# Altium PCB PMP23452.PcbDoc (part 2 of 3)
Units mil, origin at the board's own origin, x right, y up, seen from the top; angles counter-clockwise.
Board outline 4000 x 4000 mil, 6 copper layers (Top Layer, Layer 2, Layer 3, Layer 4, Layer 5, Bottom Layer), stack 40.224 mil thick; 235 components, 68 nets, 526 pads, 358 vias.
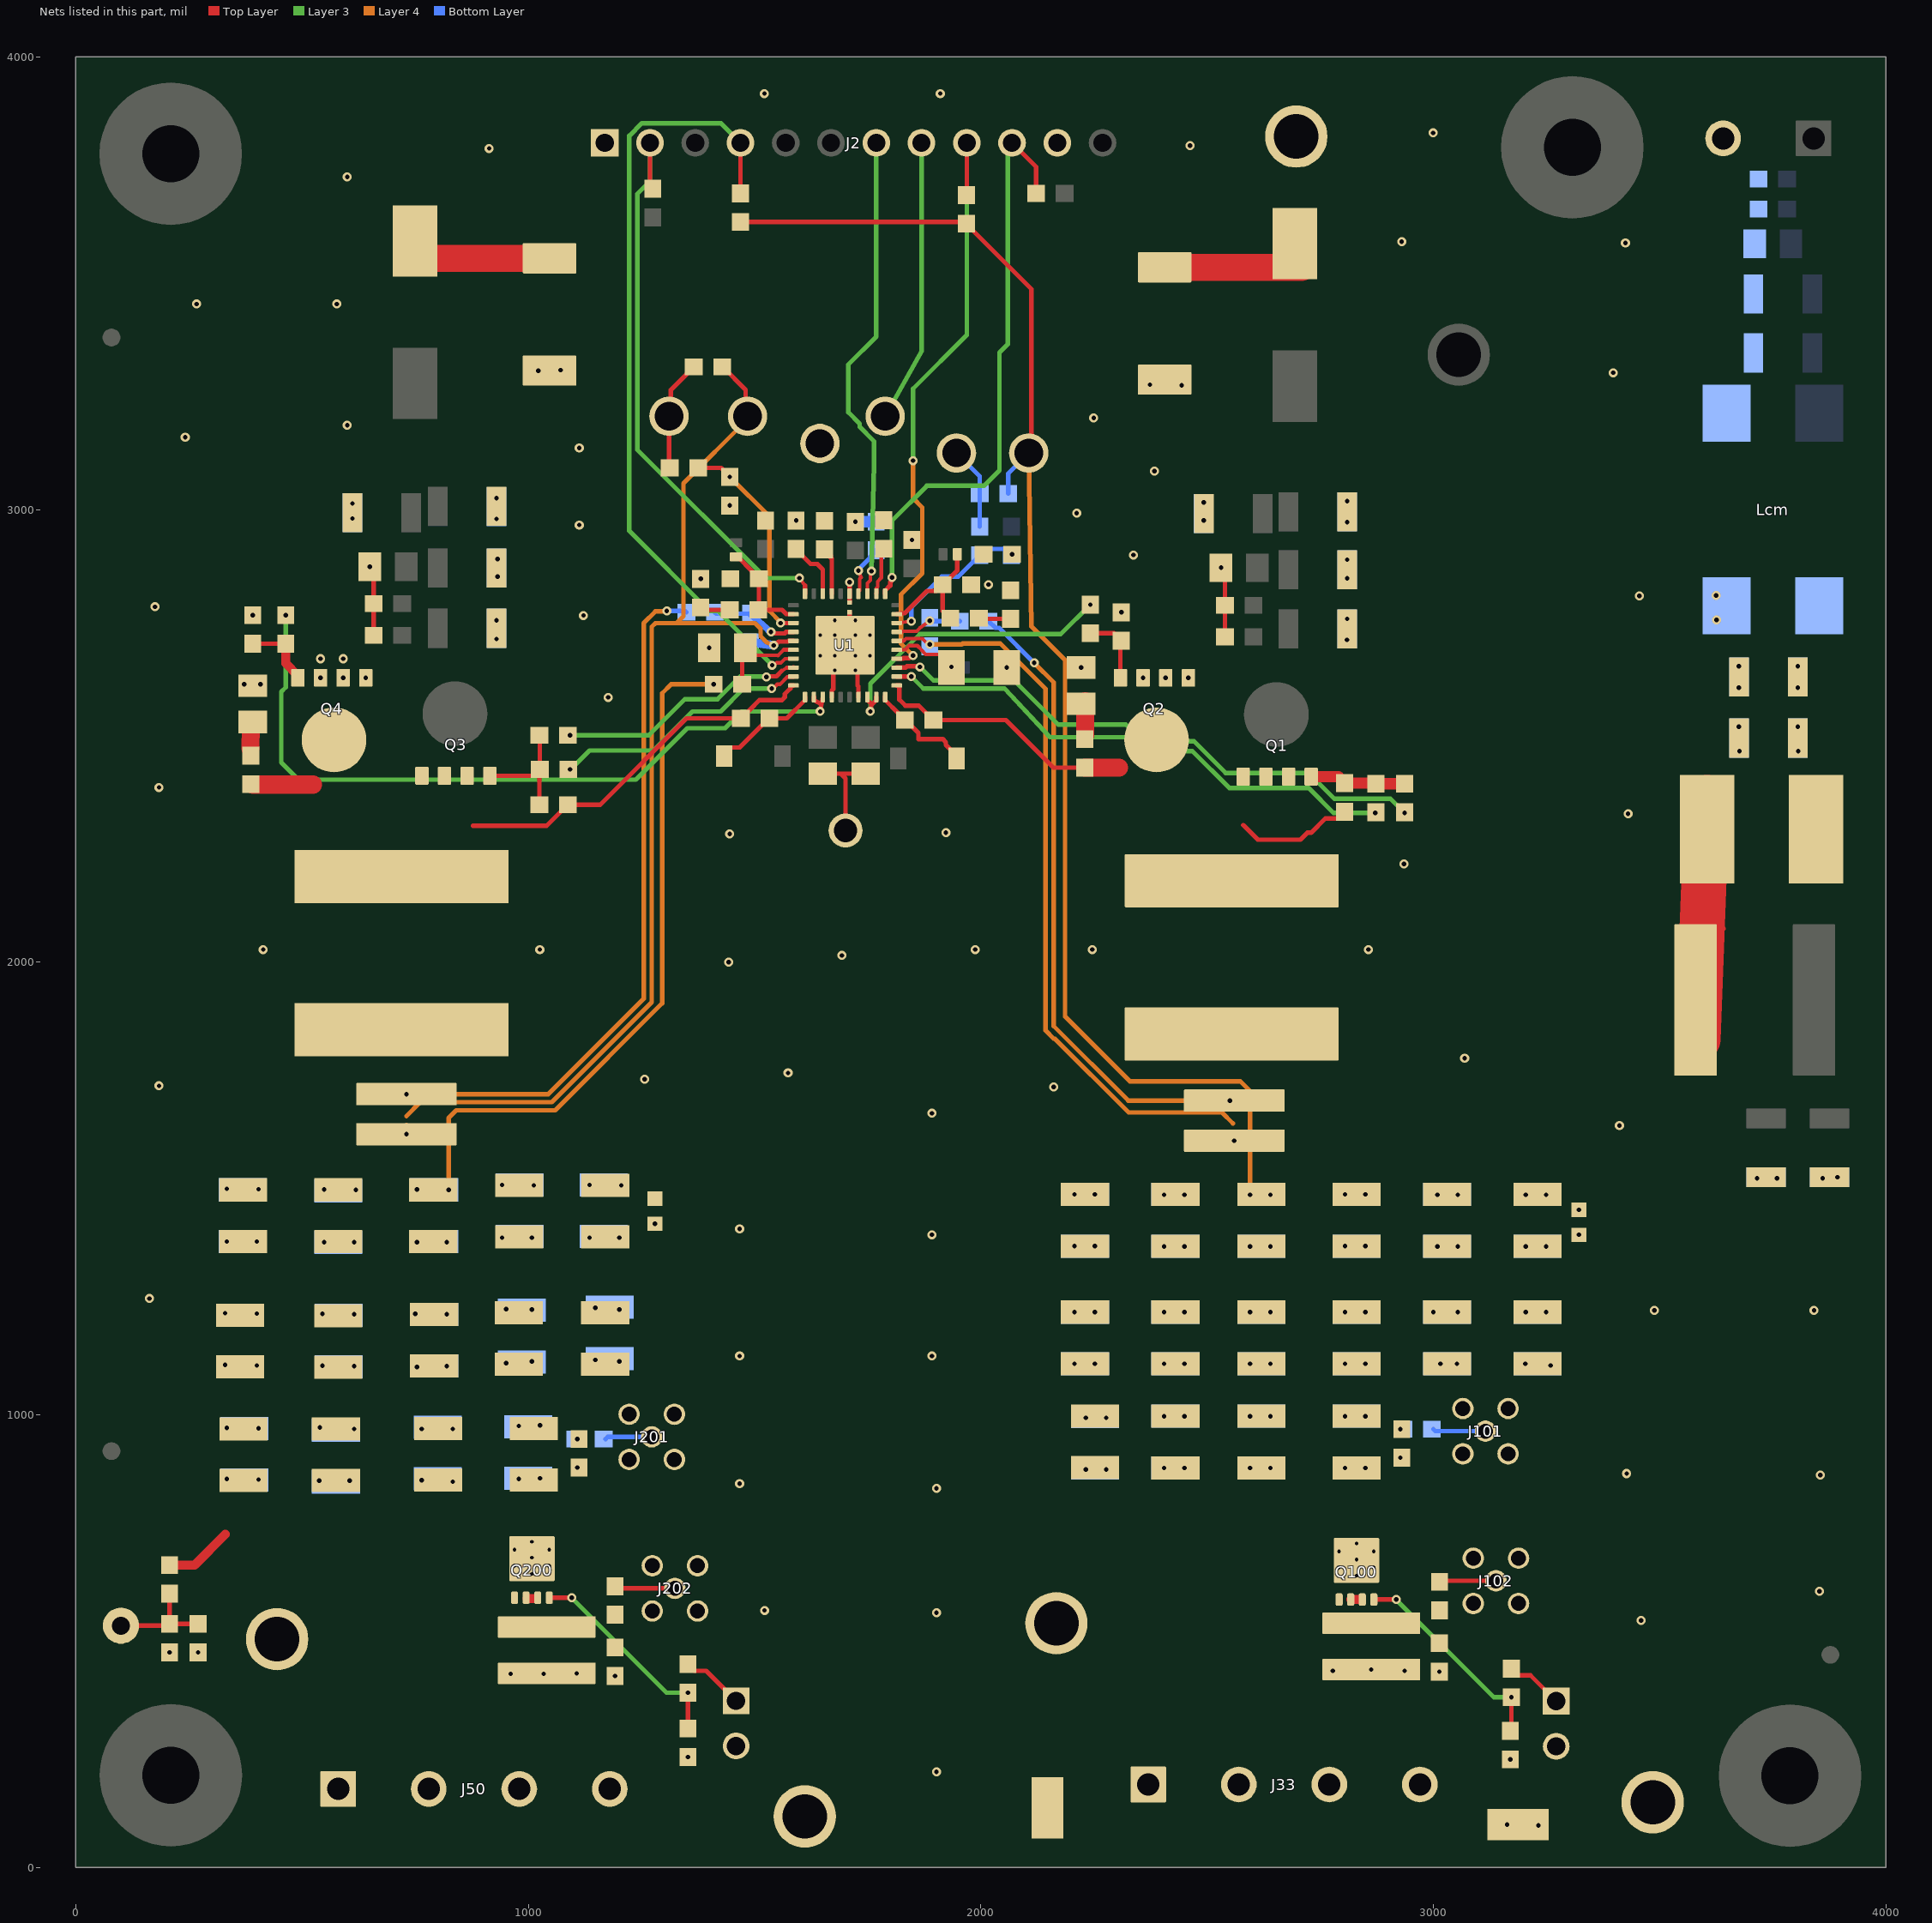
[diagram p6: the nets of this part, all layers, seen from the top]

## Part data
C1 C2 C5: library part CMP-0083622-1, "CAP, CERM, 2.2 µF, 25 V,+/- 10%, X7R, AEC-Q200 Grade 1, 0805", Cap_Case=0805, Manufacturer=MuRata, Supplier Part Number 1=490-4787-1-ND, TempCo=X7R, Tolerance_%=10%, Value2=25V, ValueDisplayed=2.2µF
C3: library part CMP-0008781-2, "CAP, CERM, 0.47 uF, 100 V, +/- 10%, X7R, AEC-Q200 Grade 1, 1206", Cap_Case=1206_180, Manufacturer=TDK, Supplier Part Number 1=445-5844-1-ND, TempCo=X7R, Tolerance_%=10%, Value1="0.007558 ohm", Value2=100V, ValueDisplayed=0.47uF
C4: library part CMP-0007138-4, "CAP, CERM, 0.47 uF, 16 V, +/- 10%, X7R, AEC-Q200 Grade 1, 0603", Cap_Case=0603, Manufacturer=MuRata, Supplier Part Number 1=490-4775-1-ND, TempCo=X7R, Tolerance_%=10%, Value1=Unknown, Value2=16V, ValueDisplayed=0.47uF
C6 C7 C30 C63 C101 C102 C201 C202 Csns5V Css1 Css2: library part CMP-0007077-5, "CAP, CERM, 0.1 uF, 25 V, +/- 10%, X7R, AEC-Q200 Grade 1, 0603", Cap_Case=0603, Manufacturer=TDK, Supplier Part Number 1=445-5667-1-ND, TempCo=X7R, Tolerance_%=10%, Value1=Unknown, Value2=25V, ValueDisplayed=0.1uF
C8 C9 C11 C12 C13 C14 C15 C19 C21 C22 C23 C24 C25 C29 C92 C93 C94 C95 C96 C97 Cpi1 Cpi2 Cpi3 Cpi4 Cpi5 Cpi6: library part CMP-0085951-1, "CAP, CERM, 10 µF, 75 V,+/- 20%, X7R, AEC-Q200 Grade 1, 1210", Cap_Case=1210, Manufacturer=TDK, TempCo=X7R, Tolerance_%=20%, Value2=75V, ValueDisplayed=10µF
C10 C20: library part CMP-0012603-3, "CAP, Polymer Hybrid, 47 uF, 80 V, +/- 20%, 36 mohm, 10x10 SMD", Manufacturer=Panasonic, Supplier Part Number 1=P15469CT-ND, Tolerance_%=20%, Value1="0.036 ohm", Value2=63V, ValueDisplayed=47uF
C16 C26 Cpi7: library part CMP-0007969-2, "CAP, CERM, 0.1 uF, 100 V, +/- 10%, X7R, AEC-Q200 Grade 1, 0805", Cap_Case=0805, Manufacturer=TDK, Supplier Part Number 1=445-5827-1-ND, TempCo=X7R, Tolerance_%=10%, Value1="0.020726 ohm", Value2=100V, ValueDisplayed=0.1uF
C17 C27 Cpi8: library part CMP-0007082-4, "CAP, CERM, 0.01 uF, 100 V, +/- 10%, X7R, AEC-Q200 Grade 1, 0603", Cap_Case=0603, Manufacturer=TDK, Supplier Part Number 1=445-5812-1-ND, TempCo=X7R, Tolerance_%=10%, Value1="0.235428 ohm", Value2=100V, ValueDisplayed=0.01uF
C18 C28 Cpi9: library part CMP-0007081-4, "CAP, CERM, 1000 pF, 100 V, +/- 10%, X7R, AEC-Q200 Grade 1, 0603", Cap_Case=0603, Manufacturer=TDK, Supplier Part Number 1=445-5806-1-ND, TempCo=X7R, Tolerance_%=10%, Value1="1.97137 ohm", Value2=100V, ValueDisplayed=1000pF
C31 C32 C33 C34 C35 C36 C37 C38 C39 C40 C41 C42 C43 C44 C45 C46 C47 C48 C49 C50 C51 C52 C53 C54 C55 C56 C57 C58 C59 C60 C61 C62 C64 C65 C66 C67 C68 C69 C70 C71 C72 C73 C74 C75 C76 C77 C78 C79 C80 C81 C82 C83 C84 C85 C86 C87 C88 C89 C90 C91: library part CMP-0009221-2, "CAP, CERM, 47 uF, 10 V, +/- 20%, X7R, 1210", Cap_Case=1210, Manufacturer=MuRata, Supplier Part Number 1=490-6543-1-ND, TempCo=X7R, Tolerance_%=20%, Value1=Unknown, Value2=10V, ValueDisplayed=47uF
Ccomp1 Ccomp2: library part CMP-0007089-5, "CAP, CERM, 6800 pF, 100 V, +/- 10%, X7R, AEC-Q200 Grade 1, 0603", Cap_Case=0603, Manufacturer=TDK, Supplier Part Number 1=445-5811-1-ND, TempCo=X7R, Tolerance_%=10%, Value1="0.35202 ohm", Value2=100V, ValueDisplayed=6800pF
Ccs1 Ccs2: library part CMP-0006897-4, "CAP, CERM, 2200 pF, 50 V, +/- 10%, X7R, 0603", Cap_Case=0603, Manufacturer=Kemet, Supplier Part Number 1=1362428, TempCo=X7R, Tolerance_%=10%, Value1=Unknown, Value2=50V, ValueDisplayed=2200pF
Cdith: library part CMP-0007468-5, "CAP, CERM, 0.01 uF, 100 V, +/- 10%, X7R, 0603", Cap_Case=0603, Manufacturer=MuRata, Supplier Part Number 1=GRM188R72A103KA01D-ND, TempCo=X7R, Tolerance_%=10%, Value1=Unknown, Value2=100V, ValueDisplayed=0.01uF
Chf1 Chf2: library part CMP-0080062-1, "CAP, CERM, 47 pF, 50 V,+/- 5%, C0G/NP0, AEC-Q200 Grade 0, 0603", Cap_Case=0603, Manufacturer=TDK, PartNumber=CGA3E2NP01H470J080AA, Supplier Part Number 1=445-12417-1-ND, TempCo=C0G/NP0, Tolerance_%=5%, Value2=50V, ValueDisplayed=47pF
Cres: library part CMP-0080102-1, "CAP, CERM, 0.22 µF, 16 V,+/- 10%, X7R, AEC-Q200 Grade 1, 0603", Cap_Case=0603, Manufacturer=Samsung, Supplier Part Number 1=1276-6868-1-ND, TempCo=X7R, Tolerance_%=10%, Value2=16V, ValueDisplayed=0.22µF
Csnu1 Csnu2: library part CMP-0007259-4, "CAP, CERM, 27 pF, 100 V, +/- 5%, C0G/NP0, 0603", Cap_Case=0603, Manufacturer=MuRata, Supplier Part Number 1=490-1337-1-ND, TempCo=C0G/NP0, Tolerance_%=5%, Value1=Unknown, Value2=100V, ValueDisplayed=27pF
D1 D3: library part CMP-0080760-2, "Diode, Schottky, 100 V, 0.15 A, AEC-Q101, SOD-123", Manufacturer=Vishay-Semiconductor, Value1=0.15A, Value2=1V
D2 D4 D5: library part CMP-0098370-1, "Diode Schottky 100V 250mA Surface Mount DFN1006BD-2", Digikey Part Number=1727-BAT46LS-QYLCT-ND, Forward Current=250mA, Manufacturer=Nexperia, Max Surge Forward Current=2.5A, Mouser Part Number=771-BAT46LS-QYL, Operating Temperature Range="to +150°C", Peak Reverse Current=9uA, ValueDisplayed=25pF
FID1 FID2 FID3: library part CMP-0077181-1, "Fiducial mark.  There is nothing to buy or mount.", Manufacturer=N/A
H3 H4 H5 H6: library part CMP-0003610-1, "Standoff, Hex, 0.5\"L #4-40 Nylon", Manufacturer=Keystone, Supplier Part Number 1=36-1902C-ND
H7 H8 H9 H10: library part CMP-0003617-1, "Machine Screw, Round, #4-40 x 1/4, Nylon, Philips panhead", Manufacturer="B&F Fastener Supply", Supplier Part Number 1=H542-ND
J1: library part CMP-0055161-1, "TEST POINT SLOTTED .118\", TH", Manufacturer=Keystone, Supplier Part Number 1=36-1040-ND
J2: library part CMP-0054586-1, "Header, 2.54 mm, 12x1, Gold, TH", Color=Black, Current_A=3A, Manufacturer="Sullins Connector Solutions", Supplier Part Number 1=S1021E-12-ND, Voltage_V=1.8kV
J11: library part CMP-0074910-1, "Terminal Block, 5.08 mm, 2x1, Brass, TH", Color=Blue, Current_A=15A, Manufacturer="On-Shore Technology", Supplier Part Number 1=ED1609-ND, Voltage_V=300V
J33 J50: library part CMP-0074939-1, "Terminal Block, 5.08 mm, 4x1, Brass, TH", Color=Blue, Current_A=15A, Manufacturer="On-Shore Technology", Supplier Part Number 1=ED2227-ND, Voltage_V=300V
J100 J200: library part CMP-0054947-1, "Header, 100mil, 2x1, Gold, TH", Manufacturer="TE Connectivity"
J101 J102 J201 J202: library part CMP-0075554-1, "Connector, MMCX 50 ohm, TH", Manufacturer=Samtec, Supplier Part Number 1=88K0549
L1: library part CMP-0090553-1, "XAL1350 Series Shielded Power Inductors 23A as RMS Current, 1 MHz Test Frequency, 30% Tolerance, 1.3uH and AEC Qualified Grade 1", Manufacturer=Coilcraft, Operating Temperature Range="to +165°C", Self Resonant Frequency=33MHz, Test Frequency=1MHz, Tolerance_%=20%
L2: library part CMP-0060967-1, "Inductor, Shielded, Composite, 2.2 uH, 24 A, 0.0042 ohm, SMD", Manufacturer=Coilcraft, Value1="0.0042 ohm", Value2=24A, ValueDisplayed=2.2uH
Lcm: library part CMP-0013118-2, "Coupled inductor, 8 A, 0.006 ohm, SMD", Manufacturer=TDK, Supplier Part Number 1=445-2212-1-ND
Logo1: library part CMP-0074844-1
LOGO2: library part CMP-0074837-2, "IEC 61010-1 Hot Surface Warning", Manufacturer="Texas Instruments"
Logo3: library part CMP-0074838-1, "Texas Instrument Corporate Signature"
Logo4: library part CMP-0074847-1, "FCC_disclaimer"
Logo5: library part CMP-0074769-3, Manufacturer="Texas Instruments"
Lpi: library part CMP-0120492-1, "10 µH Shielded Molded Inductor 12.1 A 18mOhm Max Nonstandard", Digikey Part Number=2457-XGL1060-103MEC-ND, Manufacturer=Coilcraft, Operating Temperature Range=to, Self Resonant Frequency=12MHz, Test Frequency=1MHz, Tolerance_%=20%
Lpi-hf: library part CMP-0003396-1, "Ferrite Bead, 800 ohm @ 100 MHz, 8 A, 2220", Manufacturer="Laird-Signal Integrity Products", Supplier Part Number 1=240-2433-1-ND, Value1="0.01 ohm", Value2=8A, ValueDisplayed="800 ohm"
NT1 NTv1 NTv2: library part CMP-0078142-6, "Single point connection between nets.", Manufacturer=N/A
Q1: library part CMP-0120369-1, "MOSFET N-Channel 80 V 13A (Ta), 59A (Tc) 3.7W (Ta), 73W (Tc) Surface Mount, Wettable Flank 5-DFNW (4.9x5.9) (8-SOFL-WF)", Digikey Part Number=488-NVMFS6H848NLWFT1GCT-ND, Drain To Source Breakdown Voltage=80V, Input Capacitace At Vds="1420pF @ 40V", Manufacturer=onsemi, Mouser Part Number=863-NVMFS6H848NLWFTG, Operating Temperature Range="-55°C to +175°C", Power_W=3.7W, Pulse Drain Current=319A, Typ Forward Diode Voltage=0.81V
Q2 Q4: library part CMP-0120368-2, "MOSFET N-Channel 80 V 20A (Ta), 110A (Tc) 3.8W (Ta), 116W (Tc) Surface Mount, Wettable Flank 5-DFN (5x6) (8-SOFL)", Digikey Part Number=488-NVMFS6H824NLWFT1GCT-ND, Drain To Source Breakdown Voltage=80V, Input Capacitace At Vds="2900pF @ 40V", Manufacturer=onsemi, Mouser Part Number=863-NVMFS6H824NLWFT1, Operating Temperature Range="-55°C to +175°C", Power_W=3.8W, Pulse Drain Current=722A, Typ Forward Diode Voltage=0.79V
Q3: library part CMP-0092446-1, "N-Channel 11A (Ta), 42A (Tc) 3.6W (Ta), 54W (Tc) Surface Mount 5-DFN (5x6) (8-SOFL)", Digikey Part Number=488-NVMFS6H852NLWFT1GTR-ND, Drain To Source Breakdown Voltage=80V, Input Capacitace At Vds="906pF @ 40V", Manufacturer="ON Semiconductor", Mouser Part Number=863-NVMFS6H852NLWFTG, Operating Temperature Range="-55°C to +175°C", Power_W=3.6W, Pulse Drain Current=208A, Typ Forward Diode Voltage=0.81V
Q100 Q200: library part CMP-0000593-2, "MOSFET, N-CH, 30 V, 20 A, DNH0008A (VSONP-8)", Alternate Manufacturer=None, Manufacturer="Texas Instruments", Supplier Part Number 1=296-39998-1-ND, Value1=0.014, Value2="5.3 nC"
R1 R2: library part CMP-0120372-1, "Res Metal Strip 1020 0.002 Ohm 1% 2W ±50ppm/C Sulfur Resistant Wide Terminal SMD Automotive T/R", Digikey Part Number=WSL10202L000FEA-ND, Manufacturer=Vishay, Operating Temperature Range="-65°C to +170°C", Power_W=2W, TempCo=50ppm/°C, Tolerance_%=1%
R3: library part CMP-0022900-4, "RES, 1.00, 1%, 0.1 W, 0603", Manufacturer=Yageo, Power_W=100mW, Supplier Part Number 1=311-1.00HRCT-ND, TempCo="200 ppm/C", Tolerance_%=1%, Value2=0.1W, Value_Code=1R00, ValueDisplayed=1.00
R4 R5 R7 R8 R9 R10 Rfb3-1 Rmode: library part CMP-0025697-4, "RES, 0, 5%, 0.1 W, AEC-Q200 Grade 0, 0603", Manufacturer=Vishay-Dale, Power_W=100mW, Supplier Part Number 1=541-0.0GCT-ND, TempCo="200 ppm/C", Tolerance_%=5%, Value2=0.1W, Value_Code=0000, ValueDisplayed=0
R6 R11 R12 R13 Rdivt1 Rdivt2: library part CMP-0021990-4, "RES, 100 k, 1%, 0.1 W, AEC-Q200 Grade 0, 0603", Manufacturer=Vishay-Dale, Power_W=100mW, Supplier Part Number 1=541-100KHCT-ND, TempCo="100 ppm/C", Tolerance_%=1%, Value2=0.1W, Value_Code=100k
R100 R200: library part CMP-0087671-1, "100 mOhms ±1% 2W Chip Resistor Wide 1020, 1020 Automotive AEC-Q200, Current Sense, Moisture Resistant Thick Film", Manufacturer=Vishay, PartNumber=RCWE1020R115FKEA, Power_W=2W, TempCo=100ppm/°C, Tolerance_%=1%
R101 R102 R201 R202: library part CMP-0022448-4, "RES, 49.9, 1%, 0.1 W, AEC-Q200 Grade 0, 0603", Manufacturer=Vishay-Dale, Power_W=100mW, Supplier Part Number 1=541-49.9HCT-ND, TempCo="100 ppm/C", Tolerance_%=1%, Value2=0.1W, Value_Code=49R9, ValueDisplayed=49.9
R103 R203: library part CMP-0025743-4, "RES, 1.0, 5%, 0.1 W, AEC-Q200 Grade 0, 0603", Manufacturer=Vishay-Dale, Power_W=100mW, Supplier Part Number 1=541-1.0GCT-ND, TempCo="200 ppm/C", Tolerance_%=5%, Value2=0.1W, Value_Code=1R00, ValueDisplayed=1.0
R104 R204 Rpg1 Rpg2: library part CMP-0021998-4, "RES, 10.0 k, 1%, 0.1 W, AEC-Q200 Grade 0, 0603", Manufacturer=Vishay-Dale, Power_W=100mW, Supplier Part Number 1=541-10.0KHCT-ND, TempCo="100 ppm/C", Tolerance_%=1%, Value2=0.1W, Value_Code=10k0, ValueDisplayed=10.0k
Rbode1 Rbode2: library part CMP-0025704-4, "RES, 10, 5%, 0.25 W, AEC-Q200 Grade 0, 0603", Manufacturer=Vishay-Dale, Power_W=250mW, Supplier Part Number 1=541-10SACT-ND, TempCo="200 ppm/C", Tolerance_%=5%, Value2=0.25W, Value_Code=10R0, ValueDisplayed=10
Rcomp1: library part CMP-0022042-4, "RES, 13.0 k, 1%, 0.1 W, AEC-Q200 Grade 0, 0603", Manufacturer=Vishay-Dale, Power_W=100mW, Supplier Part Number 1=541-13.0KHCT-ND, TempCo="100 ppm/C", Tolerance_%=1%, Value2=0.1W, Value_Code=13k0, ValueDisplayed=13.0k
Rcomp2: library part CMP-0022017-4, "RES, 11.3 k, 1%, 0.1 W, AEC-Q200 Grade 0, 0603", Manufacturer=Vishay-Dale, Power_W=100mW, Supplier Part Number 1=541-11.3KHCT-ND, TempCo="100 ppm/C", Tolerance_%=1%, Value2=0.1W, Value_Code=11k3, ValueDisplayed=11.3k
Rcs1 Rcs2: library part CMP-0021991-4, "RES, 100, 1%, 0.1 W, AEC-Q200 Grade 0, 0603", Manufacturer=Vishay-Dale, Power_W=100mW, Supplier Part Number 1=541-100HCT-ND, TempCo="100 ppm/C", Tolerance_%=1%, Value2=0.1W, Value_Code=100R, ValueDisplayed=100
Rd1 Rd2: library part CMP-0093440-1, "1 Ohms ±1% 1W Chip Resistor 2512 (6432 Metric) Automotive AEC-Q200, Current Sense Thick Film", Digikey Part Number=2019-SR733ATTE1R00FCT-ND, Manufacturer="KOA Speer", Mouser Part Number=660-SR733ATTE1R00F, Operating Temperature Range="-55°C to +150°C", Power_W=1W, TempCo=100ppm/°C, Tolerance_%=1%
Rdiv5-b Rdiv5-t: library part CMP-0022200-4, "RES, 200 k, 1%, 0.1 W, AEC-Q200 Grade 0, 0603", Manufacturer=Vishay-Dale, Power_W=100mW, Supplier Part Number 1=541-200KHCT-ND, TempCo="100 ppm/C", Tolerance_%=1%, Value2=0.1W, Value_Code=200k
Rdivb1: library part CMP-0022220-4, "RES, 22.1 k, 1%, 0.1 W, AEC-Q200 Grade 0, 0603", Manufacturer=Vishay-Dale, Power_W=100mW, Supplier Part Number 1=541-22.1KHCT-ND, TempCo="100 ppm/C", Tolerance_%=1%, Value2=0.1W, Value_Code=22k1, ValueDisplayed=22.1k
Rdivb2: library part CMP-0022044-4, "RES, 13.7 k, 1%, 0.1 W, AEC-Q200 Grade 0, 0603", Manufacturer=Vishay-Dale, Power_W=100mW, Supplier Part Number 1=541-13.7KHCT-ND, TempCo="100 ppm/C", Tolerance_%=1%, Value2=0.1W, Value_Code=13k7, ValueDisplayed=13.7k
Ren1 Ren2: library part CMP-0022492-4, "RES, 549 k, 1%, 0.1 W, AEC-Q200 Grade 0, 0603", Manufacturer=Vishay-Dale, Power_W=100mW, Supplier Part Number 1=541-549KHCT-ND, TempCo="100 ppm/C", Tolerance_%=1%, Value2=0.1W, Value_Code=549k
Rsnu1 Rsnu2: library part CMP-0020487-3, "RES, 1.0, 5%, 0.125 W, AEC-Q200 Grade 0, 0805", Manufacturer=Vishay-Dale, Power_W=125mW, Supplier Part Number 1=541-1.0ACT-ND, TempCo="200 ppm/C", Tolerance_%=5%, Value2=0.125W, Value_Code=1R00, ValueDisplayed=1.0
Rt: library part CMP-0022663-4, "RES, 97.6 k, 1%, 0.1 W, AEC-Q200 Grade 0, 0603", Manufacturer=Vishay-Dale, Power_W=100mW, Supplier Part Number 1=541-97.6KHCT-ND, TempCo="100 ppm/C", Tolerance_%=1%, Value2=0.1W, Value_Code=97k6, ValueDisplayed=97.6k
TP1 TP2 TP4 TP5 TP8 TP9: library part CMP-0055121-1, "Terminal, Turret, TH, Triple", Manufacturer=Keystone, Supplier Part Number 1=36-1598-2-ND
TP3 TP6: library part CMP-0055152-2, "Test Point, Miniature, SMT", Manufacturer="Keystone Electronics", Supplier Part Number 1=36-5015TR-ND
TP11 TP14: library part CMP-0055147-2, "Test Point, Multipurpose, Red, TH", Color=Red, Manufacturer="Keystone Electronics", Supplier Part Number 1=36-5010-ND
TP12 TP15: library part CMP-0055149-2, "Test Point, Multipurpose, White, TH", Color=White, Manufacturer="Keystone Electronics", Supplier Part Number 1=36-5012-ND
TP13 TP16: library part CMP-0055148-2, "Test Point, Multipurpose, Black, TH", Color=Black, Manufacturer="Keystone Electronics", Supplier Part Number 1=36-5011-ND
TPsns5V: library part CMP-0055140-2, "Test Point, Miniature, Orange, TH", Color=Orange, Manufacturer="Keystone Electronics", Supplier Part Number 1=36-5003-ND
U1: library part CMP-0094639-1, "Automotive 3.5-V to 65-V Dual Synchronous Buck Controller With Low IQ", Manufacturer="Texas Instruments", Max Supply Voltage=65V, Min Supply Voltage=3.5V, Nominal Supply Current=15-25uA, Operating Temperature Range="-40°C to +150°C", Output Voltage=0.6-55V, Switching Frequency=0.1-2.2MHz
ZZ1: library part CMP-0077236-1
ZZ2: library part CMP-0077237-1
ZZ3: library part CMP-0077238-1
ZZ7: library part CMP-0077238-1, "Place Shunt Jumper SH-J1 onto J2 pins VDDA - DEMB"

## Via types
v1: diameter 20, hole 10, Top Layer to Bottom Layer, tented both sides, 332 vias
v2: diameter 19.68, hole 7.87, Top Layer to Bottom Layer, 24 vias
v3: diameter 19.68, hole 7.87, Top Layer to Bottom Layer, tented both sides, 2 vias

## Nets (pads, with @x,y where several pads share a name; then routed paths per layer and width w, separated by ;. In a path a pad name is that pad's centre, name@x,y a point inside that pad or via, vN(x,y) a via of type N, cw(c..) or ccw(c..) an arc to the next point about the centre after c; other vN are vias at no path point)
3.3V: C30.1 C31.1 C32.1 C33.1 C34.1 C35.1 C36.1 C37.1 C38.1 C39.1 C40.1 C41.1 C42.1 C43.1 C44.1 C45.1 C46.1 C47.1 C48.1 C49.1 C50.1 C51.1 C52.1 C53.1 C54.1 C55.1 C56.1 C57.1 C58.1 C59.1 C60.1 C61.1 C62.1 C101.2 J33.1 J33.2 NTv1.2 Q100.5 Q100.6 Q100.7 Q100.8 Q100.9 R1.1 R101.2 Rbode1.2 Rpg1.2 Rpg2.2 TP3.1 TP4.1 TP11.1 | length 3179.6
  Top Layer w10: Rpg2.2@1468.62,3635.5 1964,3635.5 Rpg1.2@1968,3631.5 1968,3630.52 2111.83,3486.69 2111.83,3131.03 TP11.1@2105.76,3124.96
  Layer 4 w10: TP11.1@2105.76,3124.96 2111.83,2741.52 2186,2667.35 2186,1880 2329,1737 2573,1737 2595,1715 v1(2595,1486.38) ; NTv1.2@2557,1624 2557,1615.13 2558.09,1614.04 2558.09,1607.62 v1(2560,1605.71)
  Bottom Layer w10: Rbode1.2@2060.5,3035 2060.5,3079.69 TP11.1@2105.76,3124.96
  other v1: 2926.91,968.4 2231.77,993.62 2276.77,993.62 2405,997.09 2450,997.09 2595,997.09 2640,997.09 2804.45,997.09 2849.45,997.09 2207,1227.09 2252,1227.09 2405,1227.09 2450,1227.09 2595,1227.09 2640,1227.09 2804.45,1227.09 2849.45,1227.09 3000,1227.09 3054,1227.09 3204,1227.09 3249,1227.09 3321.5,1453.07 2405,1486.38 2450,1486.38 2640,1486.38 3009,1486.17 3054,1486.17 3204,1486.17 3249,1486.17 2207,1487.09 2252,1487.09 2804.45,1487.09 2849.45,1487.09
  other v2: 2830,644.94 2791.61,662.76 2868.39,662.76 2830,680.57 2791.61,698.39 2868.39,698.39
  other v3: 2830,716.2
5V: C63.1 C64.1 C65.1 C66.1 C67.1 C68.1 C69.1 C70.1 C71.1 C72.1 C73.1 C74.1 C75.1 C76.1 C77.1 C78.1 C79.1 C80.1 C81.1 C82.1 C83.1 C84.1 C85.1 C86.1 C87.1 C88.1 C89.1 C90.1 C91.1 C201.2 J50.1 J50.2 NTv2.2 Q200.5 Q200.6 Q200.7 Q200.8 Q200.9 R2.2 R3.2 R201.2 Rdiv5-t.2 TP8.1 | length 1719.1
  Top Layer w10: 330.89,736.43 330.89,741.26
  Top Layer w20: Rdiv5-t.2@207.21,668.26 262.72,668.26 330.89,736.43
  Layer 4 w10: v1(730.75,1620) NTv2.2@730.75,1640 ; v1(824,1497.09) 824,1655.83 841,1672.83 1059.39,1672.83 1296,1909.44 1296,2594.14 1315.71,2613.85 v1(1409.66,2613.85)
  other v1: 1108.28,946.66 615.05,969.09 764.69,969.09 833.25,969.09 334,971.49 404,970.51 539.63,972.49 979,975.36 1026,977 545.05,1223.49 615.05,1222.51 750.05,1223.49 820.05,1222.51 400.05,1223.94 330.05,1224.92 951,1233.49 1008.05,1232.51 1201.35,1232.51 1148,1236.31 619,1497.09 549,1498.07 754,1498.07 334,1499.49 404,1498.51 1012,1507.09 1205.3,1507.09 942,1508.07 1135.3,1508.07
  other v2: 1008.05,648.82 969.66,666.63 1046.43,666.63 1008.05,684.45 969.66,702.26 1046.43,702.26
  other v3: 1008.05,720.08
AGND: C4.1 Ccomp1.2 Ccomp2.2 Cdith.2 Chf1.2 Chf2.2 Cres.2 Css1.2 Css2.2 J2.8 NT1.1 Rdivb1.1 Rdivb2.1 Rmode.1 Rt.1 TP13.1 TP16.1 U1.35 | length 716.1
  Top Layer w10: NT1.1@1710.16,2794.73 1710.16,2801.87 1709.92,2802.11 1709.92,2814.09 U1.35@1709.84,2814.17 1709.92,2814.25 1709.92,2839.12 v1(1710.16,2839.36)
  Layer 3 w10: TP13.1@1788.66,3206 1868.9,3349.92 J2.8@1868.9,3810
  Bottom Layer w10: Rmode.1@1768.9,2972.93 Rmode.1@1768.9,2973.26
  Bottom Layer w25: v1(1722.87,2972.93) Rmode.1@1768.9,2972.93
  other v1: 2016.86,2834.23 1381.07,2846.9 1847.73,2932.99 1591.97,2975.94 1445.24,3009.12
COMP1: Chf1.1 D2.2 Rcomp1.2 U1.29 | length 291.2
  Top Layer w10: U1.29@1814.17,2768.9 1820.91,2768.9 1822.8,2770.79 1831.65,2770.79 1881.16,2820.29 1902,2820.29 Chf1.1@1915.7,2834 ; Rcomp1.2@1932.5,2760 1931.52,2760 1915.7,2775.82 Chf1.1@1915.7,2834 ; D2.2@1948,2901.25 1948,2865.31 1916.69,2834 Chf1.1@1915.7,2834
COMP2: Chf2.1 D4.2 Rcomp2.2 U1.2 | length 222.6
  Top Layer w10: D4.2@1459.2,2895.35 1463.13,2895.35 1494.7,2863.78 1494.7,2860.83 1508.4,2847.12 Chf2.1@1509.39,2847.12 1509.39,2779.35 Rcomp2.2@1508.31,2778.27 1560.57,2778.27 1569.87,2768.98 1585.75,2768.98 U1.2@1585.83,2768.9
DEMB: J2.7 U1.33 | length 1048.8
  Top Layer w8: U1.33@1749.21,2814.17 1749.21,2837.28 1755.71,2843.78 1755.71,2861.48 v1(1758.01,2863.78)
  Layer 3 w10: v1(1758.01,2863.78) 1764,3099 1764,3150.94 1732.29,3182.65 1732.29,3189.58 1707,3214.87 1707,3320 1768.9,3381.9 J2.7@1768.9,3810
EN1: J2.10 Ren1.1 U1.31 | length 1310
  Top Layer w10: U1.31@1788.58,2814.17 1788.58,2820.91 1799.76,2832.08 1799.76,2839.36 v1@1801.67,2841.27 ; J2.10@2068.9,3810 2122.01,3756.89 Ren1.1@2122.01,3698.5
  Layer 3 w10: v1(1803.81,2849.95) 1803.81,2975.7 1880.63,3052.52 2007.16,3052.52 2041.2,3086.56 2041.2,3346.8 2059.4,3365 2059.4,3800.51 J2.10@2068.9,3810
EN2: J2.2 Ren2.1 U1.40 | length 1308.8
  Top Layer w8: v1(1599.34,2848.72) 1611.34,2831.91
  Top Layer w10: J2.2@1268.9,3810 1268.9,3714.6 Ren2.1@1275,3708.5 ; v1(1599.34,2848.72) v1@1599.34,2849.94 ; 1611.34,2831.91 1611.34,2814.25 U1.40@1611.42,2814.17
  Layer 3 w10: J2.2@1268.9,3810 1268.9,3725.05 1241,3697.15 1241,3132.14 1524.41,2848.72 v1(1599.34,2848.72)
FB1: Rdivb1.2 Rdivt1.1 Rfb3-1.1 U1.28 | length 344.4
  Top Layer w8: U1.28@1814.17,2749.21 v1(1846.36,2753.15)
  Bottom Layer w10: v1(1846.36,2753.15) 1846.36,2784.38 1913.61,2851.62 1949.73,2851.62 1982.84,2884.74 1983.83,2884.74 1997.53,2898.44 Rdivt1.1@1997.53,2899.42 2011.23,2913.12 2053.83,2913.12 Rfb3-1.1@2067.53,2899.42
  other v1: 2068.9,2901.25
FB2: Rdivb2.2 Rdivt2.1 U1.3 | length 476.1
  Top Layer w10: Rdivt2.1@1375.5,3092 1425.86,3092 1445.24,3072.62 v1(1445.24,3072.11) ; v1(1557.28,2749.21) U1.3@1585.83,2749.21
  Layer 4 w10: v1(1445.24,3072.11) 1532.7,2984.65 1532.7,2776 1557.28,2751.42 v1(1557.28,2749.21)
NetC3_1: C3.1 D5.1 U1.25 | length 147.2
  Top Layer w8: U1.25@1814.17,2690.16 1832.06,2690.16 1841.14,2699.24 1859.55,2699.24 1868.38,2690.41 1868.38,2689.91 1878.16,2680.13 1909.45,2680.13 1934.98,2654.6 C3.1@1934.98,2650.79
  other v1: 1934.98,2652.33
NetC5_1: C5.1 R3.1 U1.6 | length 202.6
  Top Layer w8: C5.1@1479.74,2694.74 1496.61,2677.87 1550.79,2677.87 1551.53,2677.13 1564.56,2690.16
  Top Layer w10: R3.1@1472.65,2613.85 1472.65,2687.65 C5.1@1479.74,2694.74 ; 1564.56,2690.16 U1.6@1585.83,2690.16
NetC6_1: C6.1 Csnu1.1 L1.2 Q1.1 Q1.2 Q1.3 Q2.5-6 R6.1 U1.21 | length 852.2
  Top Layer w10: U1.21@1814.25,2611.34 U1.21@1814.17,2611.42 1820,2611.42 1820.08,2611.34 1820.08,2579.92 1833.35,2566.65 1862.73,2566.65 1894.3,2535.07 C6.1@1895.29,2535.07 2055.38,2535.07 2160.6,2429.85 Csnu1.1@2229.78,2429.85 ; C6.1@1880.71,2535.07 C6.1@1881.7,2535.07 ; 2305.26,2429.85 2307.34,2427.77 ; 2579.84,2302.7 2611.99,2270.55 2705.77,2270.55 2721.35,2286.13 2729.84,2286.13 2761.47,2317.75 2790.04,2317.75 2803.74,2331.45 R6.1@2803.74,2332.43
  Top Layer w40: Csnu1.1@2229.78,2429.85 2305.26,2429.85
NetC6_2: C6.2 D1.1 U1.20 | length 237.5
  Top Layer w10: U1.20@1788.66,2587.93 1788.58,2587.85 U1.20@1788.58,2585.83 1788.58,2579.09 1817.61,2550.07 1817.61,2548.77 1831.31,2535.07 C6.2@1832.3,2535.07 1833.28,2535.07 1861.81,2506.54 1861.81,2492.95 1915.7,2492.95 1922.78,2485.88 1922.78,2479.82 1946.14,2456.46 D1.1@1946.14,2450.45 ; C6.2@1817.72,2535.07 C6.2@1819.69,2535.07
NetC7_1: C7.1 Csnu2.1 L2.1 Q3.1 Q3.2 Q3.3 Q4.5-6 R13.1 U1.10 | length 998.8
  Top Layer w10: Csnu2.1@387,2393.5 Csnu2.1@395.19,2393.5 ; Csnu2.1@387,2401.7 Csnu2.1@395.19,2393.5 ; Csnu2.1@396.35,2392.35 Csnu2.1@395.19,2393.5 ; 877.62,2301.3 1040.1,2301.3 1086.51,2347.71 R13.1@1087.5,2347.71 1158.68,2347.71 1349.68,2538.7 C7.1@1469.64,2538.7 1470.62,2538.7 1498.47,2566.54 1498.47,2566.75 1510.81,2579.09 1560.9,2579.09 1566.76,2584.95 1566.76,2592.35 1579.02,2604.61 1579.02,2611.34 1579.09,2611.42 U1.10@1585.83,2611.42
  Top Layer w40: Csnu2.1@391.85,2392.35 524.15,2392.35
NetC7_2: C7.2 D3.1 U1.11 | length 240.2
  Top Layer w10: D3.1@1432.74,2455.34 1432.74,2461.34 1445.75,2474.36 1467.3,2474.36 1531.65,2538.7 C7.2@1532.63,2538.7 1571.02,2538.7 1611.42,2579.09 U1.11@1611.42,2585.83
NetC10_2: C10.2 Rd1.1 | length 297
  Top Layer w60: Rd1.1@2411.66,3535.07 C10.2@2708.68,3535.07
NetC20_2: C20.2 Rd2.2 | length 351.4
  Top Layer w10: C20.2@750,3593.46 C20.2@788.45,3555.02
  Top Layer w60: C20.2@749.98,3555.02 Rd2.2@1047,3555.02
NetC102_2: C102.2 Q100.1 Q100.2 Q100.3 R100.2 R102.1 | length 20.8
  Top Layer w20: Q100.2@2817.2,592.09 Q100.3@2838,592.09
NetC202_2: C202.2 Q200.1 Q200.2 Q200.3 R200.2 R202.1 | length 20.8
  Top Layer w20: Q200.2@997.65,594.22 Q200.3@1018.45,594.22
NetCcomp1_1: Ccomp1.1 Rcomp1.1 | length 60.2
  Top Layer w10: Rcomp1.1@1995.5,2760 1997.03,2758.47 Ccomp1.1@2055.07,2758.47
NetCcomp2_1: Ccomp2.1 Rcomp2.1 | length 66.7
  Top Layer w10: Ccomp2.1@1380.84,2783.68 1386.24,2778.27 Rcomp2.1@1445.32,2778.27
NetCcs1_1: Ccs1.1 Rcs1.1 U1.27 | length 148.6
  Top Layer w8: U1.27@1814.17,2729.53 1815.09,2730.45 1827.45,2730.45 1828.28,2731.28 1858.28,2731.28 1865,2738 v1(1887.22,2754.13)
  Bottom Layer w10: v1(1887.22,2754.13) 1888.2,2753.15 Rcs1.1@1953.63,2753.15
NetCcs1_2: Ccs1.2 NTv1.1 U1.26 | length 1624.6
  Top Layer w8: U1.26@1822.08,2709.84 1829.3,2709.84 1834.56,2715.11 1870.86,2715.11 1883.97,2702 v1(1887.22,2702)
  Layer 4 w10: v1(1887.22,2702) 1957.9,2702 1960.03,2704.13 2042.69,2704.13 2143.13,2603.69 2143.13,1848.95 2160.86,1831.22 2163.5,1831.22 2326.72,1668 2533,1668 NTv1.1@2557,1644
NetCcs2_1: Ccs2.1 NTv2.1 Rbode2.2 TP14.1 U1.5 | length 2532.5
  Top Layer w10: Rbode2.2@1428.76,3315.13 1429.74,3315.13 1480.37,3264.5 1480.37,3210.15 TP14.1@1484.52,3206 ; v1(1542.06,2700) 1544.76,2700 1553.23,2708.46 1574.16,2708.46 1575.46,2709.76 1585.75,2709.76 U1.5@1585.83,2709.84
  Layer 4 w10: NTv2.1@730.75,1660 761.46,1690.71 1051.99,1690.71 1272.87,1911.6 1272.87,2741.09 1281,2749.21 1327.81,2749.21 ; TP14.1@1484.52,3206 1484.52,3199.52 1343,3058 1343,2764.4 1327.81,2749.21 ; v1@1541.1,2700.96 1526.69,2706.65 1513.29,2720.05 1513.29,2737.07 1501.14,2749.21 1327.81,2749.21
  Bottom Layer w10: v1@1540.15,2701.91 v1(1542.06,2700)
  Bottom Layer w20: Ccs2.1@1491.22,2706.97 v1(1542.06,2700)
NetCcs2_2: Ccs2.2 Rcs2.1 U1.4 | length 201.4
  Top Layer w10: v1(1536.16,2729.53) 1538.87,2729.53 1542.06,2726.34 1566.76,2726.34 1569.87,2729.45 1585.75,2729.45 U1.4@1585.83,2729.53
  Bottom Layer w10: Rcs2.1@1412.33,2773 1415.37,2769.96 Ccs2.2@1491.22,2769.96 Ccs2.2@1491.22,2768.98 ; v1@1528.76,2731.44 1534.25,2731.44 v1(1536.16,2729.53)
  Bottom Layer w15: Ccs2.2@1491.22,2768.98 v1(1536.16,2729.53)
NetCdith_1: Cdith.1 U1.38 | length 131.7
  Top Layer w10: Cdith.1@1591.73,2912.71 1591.73,2911.73 1623.81,2879.65 1638.74,2879.65 1650.79,2867.6 U1.38@1650.79,2814.17
NetCpi3_1: Cpi3.1 Cpi4.1 Cpi5.1 Cpi6.1 Lcm.4 Lpi-hf.1
  other v1: 3805.96,2466 3804.96,2520 3804.96,2606.47 3804.96,2653.85
NetCres_1: Cres.1 U1.32 | length 106.5
  Top Layer w8: U1.32@1768.9,2814.17 1769.82,2815.09 1769.82,2826.95 1771.79,2828.92 1771.79,2840.88 1779.88,2848.98 1779.88,2907.73 1779.63,2907.98 Cres.1@1785.28,2913.63
NetCsns5V_2: Csns5V.2 Rdiv5-b.2 Rdiv5-t.1 TPsns5V.1 | length 238.9
  Top Layer w10: TPsns5V.1@100.01,534.37 203.09,534.37 Csns5V.2@207.21,538.49 ; Rdiv5-t.1@207.21,605.27 Csns5V.2@207.21,538.49 ; Rdiv5-b.2@270.48,538.49 Csns5V.2@207.21,538.49
NetCsnu1_2: Csnu1.2 Rsnu1.2 | length 75.5
  Top Layer w40: Csnu1.2@2230.21,2501.43 Rsnu1.2@2230.21,2576.91
NetCsnu2_2: Csnu2.2 Rsnu2.2 | length 46.2
  Top Layer w40: Csnu2.2@386,2472.18 Rsnu2.2@387,2518.33
NetJ100_1: J100.1 R103.1 | length 129.2
  Top Layer w10: R103.1@3172.29,439.28 3172.29,438.29 3185.99,424.59 3214.49,424.59 J100.1@3271.29,367.79
NetJ101_1: J101.1 R101.1 | length 117.1
  Bottom Layer w10: R101.1@2999.77,968.4 3004.17,964 J101.1@3115,964
NetJ102_1: J102.1 R102.2 | length 125.6
  Top Layer w10: R102.2@3013.31,631.37 3015.36,633.43 J102.1@3138.1,633.43
NetJ200_1: J200.1 R203.1 | length 140.5
  Top Layer w10: R203.1@1352.67,449.49 1352.67,448.5 1366.37,434.8 1392.78,434.8 J200.1@1459.07,368.51
NetJ201_1: J201.1 R201.1 | length 104.1
  Bottom Layer w10: R201.1@1170.78,946.66 1175.61,951.49 J201.1@1272.87,951.49
NetJ202_1: J202.1 R202.2 | length 134.4
  Top Layer w10: R202.2@1191.54,621.47 1196.22,616.8 J202.1@1324,616.8
NetL1_1: L1.1 R1.2 Rcs1.2 | length 1417
  Layer 4 w10: v1(2117.91,2661.25) 2161,2618.16 2161,1859 2325.71,1694.29 v1(2550.32,1694.29)
  Bottom Layer w10: Rcs1.2@2016.62,2753.15 2017.61,2753.15 2032.29,2738.46 2040.7,2738.46 v1(2117.91,2661.25)
NetL2_2: L2.2 R2.1 Rcs2.2 | length 1548.2
  Layer 4 w10: v1(730.75,1708.58) 1044.58,1708.58 1255,1919 1255,2749 1281,2775 1305,2775 v1(1306,2776)
  Bottom Layer w10: v1(1306,2776) 1346.34,2776 Rcs2.2@1349.34,2773
NetLpi-hf_2: Lpi-hf.2 Lpi.1 | length 631.3
  Top Layer w10: 3599.09,2116.09 3640.94,2074.24 3614.19,2101
  Top Layer w100: Lpi.1@3584.21,1830 Lpi-hf.2@3604.53,2363.93
NetQ1_4: Q1.4 R4.2 R6.2 R7.2 | length 213.7
  Top Layer w10: R6.2@2790.04,2410 2803.74,2396.3 R6.2@2803.74,2395.43 ; R4.2@2871.75,2395.43 R4.2@2873,2394.18
  Top Layer w25: Q1.4@2729.84,2410 R6.2@2790.04,2410 ; R6.2@2803.74,2395.43 R4.2@2871.75,2395.43 ; R4.2@2873,2394.18 R7.2@2936.5,2394.18
NetQ2_4: Q2.4 R10.2 R11.2 | length 158.8
  Top Layer w10: R10.2@2241.77,2726.97 2293.38,2726.97 2295.65,2724.69 2296.64,2724.69 2310.34,2710.99 R11.2@2310.34,2710.01 2308.43,2708.1 Q2.4@2308.43,2628.21
NetQ3_4: Q3.4 R5.2 R8.2 R13.2 | length 270.8
  Top Layer w10: Q3.4@915,2411.83 1010.48,2411.83 1024.52,2425.87 R5.2@1025.5,2425.87 ; R13.2@1024.5,2347.71 1024.5,2424.87 R5.2@1025.5,2425.87 ; R8.2@1024.5,2501.34 1025.5,2500.34 R5.2@1025.5,2425.87
NetQ4_4: Q4.4 R9.2 R12.2 | length 159.4
  Top Layer w10: R12.2@391,2703.49 R9.2@464.09,2703.49 ; Q4.4@491,2628.37 Q4.4@491,2633.29
  Top Layer w20: R9.2@464.09,2703.49 464.09,2660.2 Q4.4@491,2633.29
NetQ100_4: Q100.4 R103.2 R104.2 | length 468.5
  Top Layer w10: Q100.4@2868.39,592.09 v1(2917.64,592.09) ; R104.2@3169.92,302.05 3172.29,304.42 v1(3172.29,376.29)
  Layer 3 w10: v1(2917.64,592.09) 3133.44,376.29 v1(3172.29,376.29)
NetQ200_4: Q200.4 R203.2 R204.2 | length 472.6
  Top Layer w10: Q200.4@1046.45,595.98 v1(1096,596) ; v1(1352.67,386.5) 1352.67,307.48 R204.2@1353.04,307.11
  Layer 3 w10: v1(1096,596) 1305.5,386.5 v1(1352.67,386.5)
NetR4_1: R4.1 U1.22 | length 1184.2
  Top Layer w10: U1.22@1814.17,2631.1 v1(1846.36,2631.1)
  Layer 3 w10: v1(1846.36,2631.1) 1872.86,2604.61 2052,2604.61 2152.97,2496.97 2322.75,2496.97 2353.36,2466.36 2467.36,2466.36 2548.72,2385 2724,2385 2779.15,2329.85 v1(2871.55,2329.85)
NetR5_1: R5.1 U1.9 | length 584.3
  Top Layer w8: v1@1540.58,2604.61 1549.82,2613.85 1555.75,2613.85 1572.08,2630.18 1584.91,2630.18 U1.9@1585.83,2631.1
  Top Layer w10: v1(1537.87,2604.61) v1@1540.58,2604.61 ; U1.9@1580.34,2631.02 1580.42,2631.1 U1.9@1585.83,2631.1
  Layer 3 w10: v1(1092,2426) 1093.63,2426 1135.3,2467.68 1276.71,2467.68 1363,2553.96 1424.96,2553.96 1475.61,2604.61 v1(1537.87,2604.61)
NetR7_1: R7.1 U1.23 | length 1257.7
  Top Layer w10: U1.23@1814.17,2650.79 1814.25,2650.87 1833.78,2650.87 1836.89,2653.98 1863.79,2653.98 v1(1865.44,2652.33)
  Layer 3 w10: v1(1865.44,2652.33) 1895.29,2622.48 2059.4,2622.48 2062.2,2619.68 2076.32,2619.68 2171,2525 2320,2525 2357,2488 2471,2488 2541,2418 2724,2418 2781,2361 2905.14,2361 v1(2936.3,2329.85)
NetR8_1: R8.1 U1.8 | length 566.7
  Top Layer w8: 1560.37,2643.75 1571.43,2650.71 ; U1.8@1574.68,2650.87 U1.8@1585.75,2650.87
  Top Layer w10: v1(1526.23,2630.34) 1527.62,2631.72 1548.34,2631.72 1560.37,2643.75 ; 1571.43,2650.71 1585.75,2650.71 U1.8@1585.83,2650.79 U1.8@1585.75,2650.87
  Layer 3 w10: v1(1092,2501.34) 1266.34,2501.34 1346,2581 1417.9,2581 1468,2631.1 1525.47,2631.1 v1(1526.23,2630.34)
NetR9_1: R9.1 U1.12 U1.13 | length 1659.7
  Top Layer w10: U1.12@1631.1,2585.83 1631.1,2579.09 1647.83,2569.89 ; v1@1642.97,2555.88 v1(1644.88,2553.96) 1647.83,2569.89 ; U1.13@1650.79,2585.83 1647.83,2569.89
  Layer 3 w10: v1(464.09,2766.49) 464.09,2607.44 454,2597.34 454,2441 491.87,2403.13 1237.44,2403.13 1351.32,2517 1435,2517 1471.96,2553.96 v1(1644.88,2553.96)
NetR10_1: R10.1 U1.18 U1.19 | length 678.3
  Top Layer w10: U1.18@1749.21,2585.83 1749.21,2579.09 1757.75,2570.55 1757.75,2567.95 ; v1(1755.84,2553.96) 1757.75,2555.88 1757.75,2567.95 ; U1.19@1768.9,2585.83 1768.9,2579.09 1757.75,2567.95
  Layer 3 w10: v1(1755.84,2553.96) 1755.84,2615.35 1865.36,2724.87 2176.69,2724.87 v1(2241.77,2789.96)
NetRbode1_1: Rbode1.1 Rdivt1.2 TP12.1 | length 188
  Bottom Layer w10: TP12.1@1950.36,3124.96 TP12.1@1946.14,3124.96 1997.5,3073.59 Rbode1.1@1997.5,3035 Rdivt1.2@1997.53,2962.41
NetRbode2_1: Rbode2.1 Rdivt2.2 TP15.1 | length 247
  Top Layer w10: Rdivt2.2@1312.5,3092 1311,3093.5 TP15.1@1311,3206 1315.14,3210.14 1315.14,3264.5 1351.08,3300.44 1351.08,3301.43 1364.78,3315.13 Rbode2.1@1365.77,3315.13
NetRmode_2: Rmode.2 U1.34 | length 109
  Top Layer w8: v1(1729.53,2865.31) 1735.33,2849.95 1732.42,2847.04 U1.34@1732.42,2820.91
  Top Layer w10: v1@1729.53,2864.26 v1(1729.53,2865.31)
  Bottom Layer w10: v1(1729.53,2865.31) 1729.53,2867.65 1755.12,2893.24 1755.12,2895.51 1768.9,2909.29 Rmode.2@1768.9,2910.27
NetRt_2: Rt.2 U1.37 | length 104.6
  Top Layer w10: Rt.2@1654.72,2912.2 1668.43,2898.5 1668.43,2893.75 1670.47,2891.7 U1.37@1670.47,2814.17
PG1: J2.9 Rpg1.1 U1.24 | length 1375.5
  Top Layer w10: U1.24@1814.17,2670.47 1814.25,2670.55 1828.18,2670.55 1829.48,2671.85 1841.98,2671.85 1847.49,2677.36 v1(1850.2,2677.36) ; Rpg1.1@1968,3694.5 1968.9,3695.39 J2.9@1968.9,3810
  Layer 3 w10: v1(1850.35,3108) 1850.2,3266.73 1968.9,3385.43 J2.9@1968.9,3810
  Layer 4 w10: v1(1850.2,2677.36) 1823.49,2704.07 1823.49,2811.98 1870.6,2859.1 1870.6,3004.28 1850.35,3024.53 v1(1850.35,3108)
PG2: J2.4 Rpg2.1 U1.7 | length 1752
  Top Layer w8: v1@1538.87,2654.6 1542.12,2654.6 1548.77,2661.25 1558.11,2661.25 1567.33,2670.47 U1.7@1585.83,2670.47
  Top Layer w10: Rpg2.1@1468.62,3698.5 1468.9,3698.77 J2.4@1468.9,3810
  Layer 3 w10: J2.4@1468.9,3810 1425.51,3853.39 1250.93,3853.39 1223.13,3825.59 1223.13,2952.62 1399.74,2776 1418.87,2776 v1(1538.87,2656)
PGND: C1.2 C2.2 C3.2 C5.2 C8.2 C9.2 C11.2 C12.2 C13.2 C14.2 C15.2 C16.2 C17.2 C18.2 C19.2 C21.2 C22.2 C23.2 C24.2 C25.2 C26.2 C27.2 C28.2 C29.2 C30.2 C31.2 C32.2 C33.2 C34.2 C35.2 C36.2 C37.2 C38.2 C39.2 C40.2 C41.2 C42.2 C43.2 C44.2 C45.2 C46.2 C47.2 C48.2 C49.2 C50.2 C51.2 C52.2 C53.2 C54.2 C55.2 C56.2 C57.2 C58.2 C59.2 C60.2 C61.2 C62.2 C63.2 C64.2 C65.2 C66.2 C67.2 C68.2 C69.2 C70.2 C71.2 C72.2 C73.2 C74.2 C75.2 C76.2 C77.2 C78.2 C79.2 C80.2 C81.2 C82.2 C83.2 C84.2 C85.2 C86.2 C87.2 C88.2 C89.2 C90.2 C91.2 C92.2 C93.2 C94.2 C95.2 C96.2 C97.2 C101.1 C102.1 C201.1 C202.1 Cpi3.2 Cpi4.2 Cpi5.2 Cpi6.2 Csns5V.1 J1.1 J2.1 J2.11 J33.3 J33.4 J50.3 J50.4 J100.2 J101.2 J101.3 J101.4 J101.5 J102.2 J102.3 J102.4 J102.5 J200.2 J201.2 J201.3 J201.4 J201.5 J202.2 J202.3 J202.4 J202.5 Lcm.3 NT1.2 Q2.1 Q2.2 Q2.3 Q4.1 Q4.2 Q4.3 R11.1 R12.1 R100.1 R104.1 R200.1 R204.1 Rd1.2 Rd2.1 Rdiv5-b.1 Rsnu1.1 Rsnu2.1 TP2.1 TP5.1 TP6.1 TP9.1 U1.14 U1.17 U1.41 | length 736.5
  Top Layer w10: v1(650,2873.5) 658.5,2865 C27.2@658.5,2792.01 C28.2@658.5,2722.01 ; C1.2@1650.79,2416.46 1690.79,2416.46 ; U1.14@1670.47,2585.83 1670.55,2585.91 1670.55,2600.01 1674.01,2603.47 1674.01,2641.53 v2(1677.36,2644.88) ; U1.41@1700,2700 1710,2710 NT1.2@1710,2773 ; J1.1@1701,2291 1701,2406.24 1690.79,2416.46 ; v2(1722.64,2644.88) 1727.43,2640.09 1727.43,2611.34 1729.53,2609.24 U1.17@1729.53,2585.83 ; C2.2@1745.28,2416.46 1690.79,2416.46 ; v1(2530.71,2871.5) 2539.22,2862.99 C17.2@2539.22,2788.58 C18.2@2539.22,2718.7
  other v1: 3232,93 3162.59,95 1902,211.67 3169.92,239.06 1353.04,244.12 1191.76,423.14 961,428 1034.13,428 1106.85,428.97 3012.97,432.51 2777.8,434.5 2936.5,434.5 2862.63,437.46 207.21,475.5 270.48,475.5 3459,546 1902,562.83 1522,568.04 3852.82,610.51 1902,837.64 1467,848.33 833.25,852.51 538.23,854.91 605.47,854.91 764.69,855.91 404,857.34 334,858.32 979,858.32 1026,859.91 3855,867.28 3427,870.38 2231.77,879.45 2276.77,879.45 2405,882.91 2450,882.91 2595,882.91 2640,882.91 2804.45,882.91 2849.45,882.91 1108.28,883.67 2926.91,905.41 754,1105.91 615.05,1107.91 820.05,1107.91 400.05,1109.34 545.05,1108.89 3259,1109 330.05,1110.32 2207,1112.91 2252,1112.91 2405,1112.91 2450,1112.91 2595,1112.91 2640,1112.91 2804.45,1112.91 2849.45,1112.91 3015.36,1112.91 3052.02,1112.91 3203.24,1112.91 951,1114.51 1008.05,1117.91 1201.35,1117.91 1148,1121.51 1467,1130.11 1892,1130.11 3488,1231 3840.91,1231 163,1257 2405,1372.21 2450,1372.21 2595,1372.21 2640,1372.21 3009,1372 3054,1372 3204,1372 3249,1372 2207,1372.91 2252,1372.91 2804.45,1372.91 2849.45,1372.91 549,1381.49 615.05,1381.49 754,1381.49 820.05,1381.49 334,1382.91 400.05,1382.91 942,1391.49 1008.05,1391.49 1135.3,1391.49 1201.35,1391.49 1892,1398 3321.5,1397.95 1467,1410.86 1280,1422.44 3715,1522.68 3759,1522.68 3860,1522.68 3892.85,1525.04 3411,1639 1891.65,1666.34 2161,1724.29 184,1727 1257.22,1741.49 1574.01,1755.41 3069,1788 1443,2000 1692.87,2015 414.2,2028 1025.5,2028 1987.45,2028 2246.38,2028 2856.14,2028 2935,2217 1445,2283.28 1922.78,2286.13 3430,2328 184,2386 3676.04,2466.04 3675.04,2520.04 1176.71,2584.95 3675.04,2606.51 372,2614 408,2614 541,2628.37 591,2628.37 641,2628.37 2358.43,2628.21 2408.43,2628.21 2458.43,2628.21 2057.02,2650.79 2221.3,2650.87 3675.04,2653.89 541,2670.47 591,2670.47 1399.74,2694.74 2809.13,2712 929.76,2714.19 929.96,2755.19 3625.75,2756 2809.57,2758.47 391,2766.49 1122,2765.94 2310.34,2773 175.3,2785.19 3454.89,2809.43 3624.75,2810 2809.57,2848.19 931.91,2851.62 2809.57,2889.44 931.91,2890.43 2337.08,2899.53 1112.63,2965.95 2809.57,2972.23 2492.68,2975.7 929.76,2979.12 611.28,2980.4 2211.77,2991.88 611.28,3013.38 2492.68,3016 2809.57,3018.51 929.76,3025.47 2383.43,3084.94 1112.63,3135.96 242,3160 600,3186.48 2249.43,3202.27 2443.67,3274.25 2373.39,3275.71 3397,3302.21 1022,3306.67 1071.47,3308.13 267.17,3454 577,3454 3424.27,3588.96 2929.86,3591.82 600,3735 913.49,3797.63 2462.09,3804.1 2999.33,3832 1521.83,3919 1910.32,3919
  other v2: 1644.88,2677.36 1677.36,2677.36 1722.64,2677.36 1755.12,2677.36 1644.88,2722.64 1677.36,2722.64 1722.64,2722.64 1755.12,2722.64 1677.36,2755.12 1722.64,2755.12
PGND-ext: Cpi1.2 Cpi2.2 Cpi7.2 Cpi8.2 Cpi9.2 J11.2 Lcm.2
